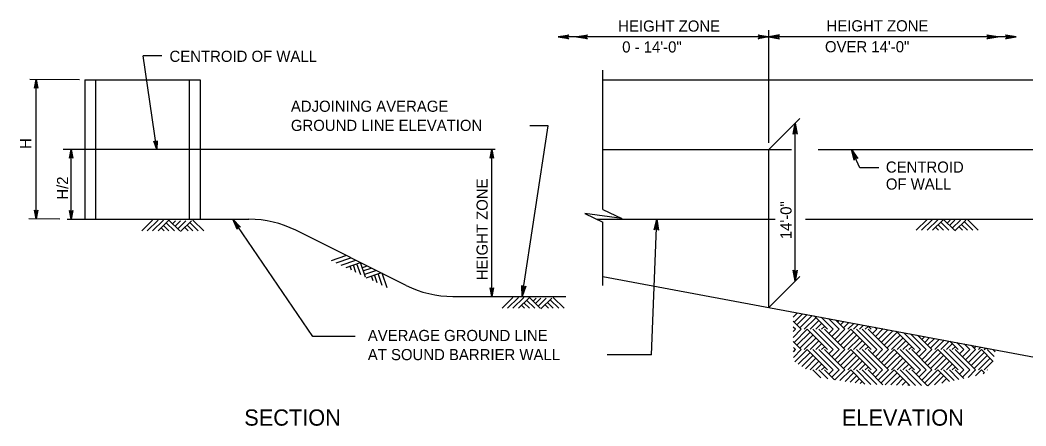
# Model space of a CAD drawing. Extents: x 3385 to 6532, y -616 to 1166.
# Drawn here: x 4114.7 to 4391.8, y 868.5 to 980.4 of the extents above; entities that cross this region are included whole.
import ezdxf

# ---------------------------------------------------------------- set-up
doc = ezdxf.new("R2010")
doc.units = 0
doc.layers.add('1', color=7, linetype='Continuous')

msp = doc.modelspace()

# ---------------------------------------------------------------- linework, layer by layer
at = {"layer": '1'}
for p, q in [((4389.13, 975.76), (4262.87, 975.76)), ((4320.95, 946.55), (4320.95, 977.59)), ((4153.71, 970.51), (4148.63, 970.51)), ((4152.34, 944.69), (4148.63, 970.51)), ((4275.26, 928.19), (4275.26, 966.59)), ((4131.05, 963.89), (4117.4, 964)), ((4119.09, 925.6), (4119.09, 964)), ((4132.47, 963.89), (4132.47, 925.49)), ((4132.47, 963.89), (4164.27, 963.89)), ((4135.47, 963.89), (4135.47, 925.49)), ((4161.27, 963.89), (4161.27, 925.49)), ((4164.27, 963.89), (4164.27, 925.49)), ((4275.26, 963.89), (4416.34, 963.89)), ((4320.95, 944.69), (4329.48, 953.22)), ((4253, 904.21), (4260.16, 951.24)), ((4260.16, 951.24), (4255.08, 951.24)), ((4328.22, 908.41), (4328.22, 951.96)), ((4245.56, 944.69), (4126.55, 944.69)), ((4128.74, 925.49), (4128.74, 944.69)), ((4244.62, 904.21), (4244.62, 944.69)), ((4275.26, 944.69), (4327.19, 944.69)), ((4320.95, 901.15), (4320.95, 944.69)), ((4334.55, 944.69), (4425.74, 944.69)), ((4346.02, 939.62), (4343.74, 944.69)), ((4351.29, 939.62), (4346.02, 939.62)), ((4125.61, 925.49), (4117.09, 925.56)), ((4127.65, 925.49), (4177.74, 925.49)), ((4195.37, 893.19), (4173.27, 925.49)), ((4273.54, 925.49), (4322.71, 925.49)), ((4288.66, 888.05), (4290.07, 925.49)), ((4331.03, 925.49), (4416.34, 925.49)), ((4361.55, 922.44), (4364.56, 925.45)), ((4363.05, 922.44), (4366.06, 925.45)), ((4364.55, 922.44), (4367.56, 925.45)), ((4366.05, 922.44), (4369.06, 925.45)), ((4372.06, 922.44), (4369.06, 925.45)), ((4378.65, 922.44), (4375.65, 925.45)), ((4148.18, 922.25), (4151.18, 925.26)), ((4149.68, 922.25), (4152.68, 925.26)), ((4151.18, 922.25), (4154.18, 925.26)), ((4152.68, 922.25), (4155.68, 925.26)), ((4154.36, 922.31), (4153.53, 923.14)), ((4155.68, 922.25), (4154.18, 923.76)), ((4157.18, 922.25), (4154.93, 924.51)), ((4158.68, 922.25), (4155.68, 925.26)), ((4157.53, 925.02), (4156.71, 924.2)), ((4158.86, 925.08), (4157.36, 923.58)), ((4160.36, 925.08), (4158.11, 922.83)), ((4161.86, 925.08), (4158.86, 922.08)), ((4160.95, 922.31), (4160.12, 923.14)), ((4162.27, 922.25), (4160.77, 923.76)), ((4163.77, 922.25), (4161.52, 924.51)), ((4165.27, 922.25), (4162.27, 925.26)), ((4275.26, 907.17), (4275.26, 924.69)), ((4367.73, 922.5), (4366.91, 923.33)), ((4369.06, 922.44), (4367.56, 923.95)), ((4370.56, 922.44), (4368.31, 924.7)), ((4370.91, 925.21), (4370.08, 924.39)), ((4372.23, 925.27), (4370.73, 923.77)), ((4373.73, 925.27), (4371.48, 923.02)), ((4375.23, 925.27), (4372.23, 922.27)), ((4374.32, 922.5), (4373.5, 923.33)), ((4375.65, 922.44), (4374.15, 923.95)), ((4377.15, 922.44), (4374.9, 924.7)), ((4221.02, 907.25), (4190.62, 922.45)), ((4200.44, 914.14), (4204.46, 915.5)), ((4201.78, 913.48), (4205.81, 914.84)), ((4203.13, 912.81), (4207.15, 914.17)), ((4204.47, 912.15), (4208.5, 913.51)), ((4206, 911.46), (4205.63, 912.56)), ((4207.17, 910.82), (4206.49, 912.83)), ((4208.51, 910.15), (4207.49, 913.17)), ((4209.86, 909.49), (4208.5, 913.51)), ((4210.05, 912.48), (4208.95, 912.1)), ((4211.27, 911.94), (4209.26, 911.26)), ((4212.61, 911.28), (4209.6, 910.26)), ((4213.96, 910.61), (4209.94, 909.25)), ((4211.91, 908.54), (4211.54, 909.64)), ((4213.08, 907.9), (4212.39, 909.91)), ((4214.42, 907.24), (4213.4, 910.25)), ((4215.77, 906.57), (4214.4, 910.59)), ((4275.26, 909.69), (4416.34, 883.3)), ((4320.95, 901.15), (4329.48, 909.68)), ((4233.9, 904.21), (4265, 904.21)), ((4247.46, 900.92), (4250.47, 903.92)), ((4248.96, 900.92), (4251.97, 903.92)), ((4250.46, 900.92), (4253.47, 903.92)), ((4251.96, 900.92), (4254.97, 903.92)), ((4257.97, 900.92), (4254.97, 903.92)), ((4256.82, 903.69), (4255.99, 902.86)), ((4258.14, 903.75), (4256.64, 902.24)), ((4259.64, 903.75), (4257.39, 901.49)), ((4261.14, 903.75), (4258.14, 900.74)), ((4264.56, 900.92), (4261.56, 903.92)), ((4253.64, 900.98), (4252.82, 901.8)), ((4254.97, 900.92), (4253.47, 902.42)), ((4256.47, 900.92), (4254.22, 903.17)), ((4260.23, 900.98), (4259.41, 901.8)), ((4261.56, 900.92), (4260.06, 902.42)), ((4263.06, 900.92), (4260.81, 903.17)), ((4327.65, 898.48), (4328.84, 899.67)), ((4327.9, 897.13), (4330.19, 899.42)), ((4328.7, 896.33), (4331.53, 899.17)), ((4329.5, 895.53), (4332.88, 898.91)), ((4330.7, 895.13), (4333.9, 898.33)), ((4337.1, 895.13), (4333.41, 898.81)), ((4338.7, 895.13), (4335.38, 898.45)), ((4340.3, 895.13), (4337.35, 898.08)), ((4329.9, 895.13), (4327.65, 897.37)), ((4328.3, 895.13), (4327.66, 895.76)), ((4327.67, 894.5), (4328.3, 895.13)), ((4327.68, 892.91), (4329.9, 895.13)), ((4327.9, 891.53), (4331.5, 895.13)), ((4337.1, 889.53), (4331.5, 895.13)), ((4332.3, 895.13), (4334.7, 897.53)), ((4338.7, 889.53), (4333.1, 895.13)), ((4333.9, 895.13), (4335.5, 896.73)), ((4340.3, 889.53), (4334.7, 895.13)), ((4335.5, 895.13), (4336.3, 895.93)), ((4341.9, 889.53), (4336.3, 895.13)), ((4337.5, 893.93), (4338.7, 895.13)), ((4338.3, 893.13), (4340.3, 895.13)), ((4339.1, 892.33), (4341.9, 895.13)), ((4341.9, 895.13), (4339.32, 897.71)), ((4339.9, 897.13), (4340.29, 897.53)), ((4339.9, 891.53), (4343.5, 895.13)), ((4340.7, 896.33), (4341.64, 897.27)), ((4341.5, 895.53), (4342.99, 897.02)), ((4342.7, 895.13), (4344.34, 896.77)), ((4349.1, 889.53), (4343.5, 895.13)), ((4344.3, 895.13), (4345.69, 896.52)), ((4350.7, 889.53), (4345.1, 895.13)), ((4345.9, 895.13), (4347.03, 896.27)), ((4352.3, 889.53), (4346.7, 895.13)), ((4347.5, 895.13), (4348.3, 895.93)), ((4349.1, 895.13), (4348.18, 896.05)), ((4353.9, 889.53), (4348.3, 895.13)), ((4349.5, 893.93), (4350.7, 895.13)), ((4350.7, 895.13), (4350.14, 895.68)), ((4350.3, 893.13), (4352.3, 895.13)), ((4351.1, 892.33), (4353.77, 895)), ((4352.3, 895.13), (4352.11, 895.31)), ((4206.95, 893.19), (4195.37, 893.19)), ((4328.7, 890.73), (4332.3, 894.33)), ((4329.5, 889.93), (4333.1, 893.53)), ((4330.7, 889.53), (4333.9, 892.73)), ((4340.7, 890.73), (4344.3, 894.33)), ((4341.5, 889.93), (4345.1, 893.53)), ((4342.7, 889.53), (4345.9, 892.73)), ((4351.9, 891.53), (4355.12, 894.75)), ((4352.7, 890.73), (4355.5, 893.53)), ((4355.5, 893.53), (4356.3, 894.33)), ((4355.5, 891.93), (4357.1, 893.53)), ((4355.5, 890.33), (4357.9, 892.73)), ((4361.1, 889.53), (4356.05, 894.58)), ((4362.7, 889.53), (4358.02, 894.21)), ((4364.3, 889.53), (4359.99, 893.84)), ((4365.9, 889.53), (4361.95, 893.47)), ((4362.3, 893.13), (4362.53, 893.36)), ((4363.1, 892.33), (4363.88, 893.11)), ((4363.9, 891.53), (4365.23, 892.86)), ((4364.7, 890.73), (4366.58, 892.61)), ((4365.5, 889.93), (4367.92, 892.36)), ((4329.9, 889.53), (4327.69, 891.74)), ((4328.3, 889.53), (4327.7, 890.13)), ((4327.71, 887.35), (4329.9, 889.53)), ((4327.71, 888.94), (4328.3, 889.53)), ((4328.08, 886.12), (4331.5, 889.53)), ((4337.1, 883.93), (4331.5, 889.53)), ((4332.3, 889.53), (4334.7, 891.93)), ((4338.7, 883.93), (4333.1, 889.53)), ((4333.9, 889.53), (4335.5, 891.13)), ((4340.3, 883.93), (4334.7, 889.53)), ((4335.5, 889.53), (4336.3, 890.33)), ((4341.9, 883.93), (4336.3, 889.53)), ((4337.5, 888.33), (4338.7, 889.53)), ((4338.3, 887.53), (4340.3, 889.53)), ((4339.1, 886.73), (4341.9, 889.53)), ((4339.9, 885.93), (4343.5, 889.53)), ((4349.1, 883.93), (4343.5, 889.53)), ((4344.3, 889.53), (4346.7, 891.93)), ((4350.7, 883.93), (4345.1, 889.53)), ((4345.9, 889.53), (4347.5, 891.13)), ((4352.3, 883.93), (4346.7, 889.53)), ((4347.5, 889.53), (4348.3, 890.33)), ((4353.9, 883.93), (4348.3, 889.53)), ((4349.5, 888.33), (4350.7, 889.53)), ((4350.3, 887.53), (4352.3, 889.53)), ((4351.1, 886.73), (4353.9, 889.53)), ((4351.9, 885.93), (4355.5, 889.53)), ((4353.5, 889.93), (4355.5, 891.93)), ((4354.7, 889.53), (4355.5, 890.33)), ((4361.1, 883.93), (4355.5, 889.53)), ((4356.3, 889.53), (4358.7, 891.93)), ((4362.7, 883.93), (4357.1, 889.53)), ((4357.9, 889.53), (4359.5, 891.13)), ((4364.3, 883.93), (4358.7, 889.53)), ((4359.5, 889.53), (4360.3, 890.33)), ((4365.9, 883.93), (4360.3, 889.53)), ((4361.5, 888.33), (4362.7, 889.53)), ((4362.3, 887.53), (4364.3, 889.53)), ((4363.1, 886.73), (4365.9, 889.53)), ((4363.9, 885.93), (4367.5, 889.53)), ((4366.7, 889.53), (4369.27, 892.1)), ((4373.1, 883.93), (4367.5, 889.53)), ((4368.3, 889.53), (4370.62, 891.85)), ((4374.7, 883.93), (4369.1, 889.53)), ((4369.9, 889.53), (4371.5, 891.13)), ((4376.3, 883.93), (4370.7, 889.53)), ((4373.1, 889.53), (4370.81, 891.82)), ((4371.5, 889.53), (4372.3, 890.33)), ((4377.9, 883.93), (4372.3, 889.53)), ((4374.7, 889.53), (4372.78, 891.45)), ((4373.5, 888.33), (4374.7, 889.53)), ((4374.3, 887.53), (4376.3, 889.53)), ((4376.3, 889.53), (4374.75, 891.08)), ((4375.1, 886.73), (4377.9, 889.53)), ((4375.9, 885.93), (4379.5, 889.53)), ((4377.9, 889.53), (4376.72, 890.71)), ((4377.5, 889.93), (4378.03, 890.46)), ((4378.7, 889.53), (4379.38, 890.21)), ((4382.74, 886.28), (4379.5, 889.53)), ((4380.3, 889.53), (4380.73, 889.96)), ((4383, 887.62), (4381.1, 889.53)), ((4381.9, 889.53), (4382.08, 889.71)), ((4383.27, 888.96), (4382.7, 889.53)), ((4288.66, 888.05), (4276.44, 888.05)), ((4329.07, 885.5), (4332.3, 888.73)), ((4330.05, 884.88), (4333.1, 887.93)), ((4331.03, 884.26), (4333.9, 887.13)), ((4340.7, 885.13), (4344.3, 888.73)), ((4341.5, 884.33), (4345.1, 887.93)), ((4342.7, 883.93), (4345.9, 887.13)), ((4352.7, 885.13), (4355.5, 887.93)), ((4355.5, 887.93), (4356.3, 888.73)), ((4355.5, 886.33), (4357.1, 887.93)), ((4355.5, 884.73), (4357.9, 887.13)), ((4364.7, 885.13), (4368.3, 888.73)), ((4365.5, 884.33), (4369.1, 887.93)), ((4366.7, 883.93), (4369.9, 887.13)), ((4376.7, 885.13), (4380.3, 888.73)), ((4377.5, 884.33), (4381.1, 887.93)), ((4378.7, 883.93), (4381.9, 887.13)), ((4332.3, 883.93), (4334.7, 886.33)), ((4335.31, 881.72), (4333.1, 883.93)), ((4333.9, 883.93), (4335.5, 885.53)), ((4337.17, 881.45), (4334.7, 883.93)), ((4335.5, 883.93), (4336.3, 884.73)), ((4339.04, 881.19), (4336.3, 883.93)), ((4337.5, 882.73), (4338.7, 883.93)), ((4338.3, 881.93), (4340.3, 883.93)), ((4339.14, 881.17), (4341.9, 883.93)), ((4340.54, 880.97), (4343.5, 883.93)), ((4347.44, 879.99), (4343.5, 883.93)), ((4344.3, 883.93), (4346.7, 886.33)), ((4349.09, 879.94), (4345.1, 883.93)), ((4345.9, 883.93), (4347.5, 885.53)), ((4350.73, 879.9), (4346.7, 883.93)), ((4347.5, 883.93), (4348.3, 884.73)), ((4352.37, 879.86), (4348.3, 883.93)), ((4349.5, 882.73), (4350.7, 883.93)), ((4350.3, 881.93), (4352.3, 883.93)), ((4351.1, 881.13), (4353.9, 883.93)), ((4351.9, 880.33), (4355.5, 883.93)), ((4353.5, 884.33), (4355.5, 886.33)), ((4354.7, 883.93), (4355.5, 884.73)), ((4359.75, 879.67), (4355.5, 883.93)), ((4356.3, 883.93), (4358.7, 886.33)), ((4361.39, 879.63), (4357.1, 883.93)), ((4357.9, 883.93), (4359.5, 885.53)), ((4363.04, 879.59), (4358.7, 883.93)), ((4359.5, 883.93), (4360.3, 884.73)), ((4364.68, 879.55), (4360.3, 883.93)), ((4361.5, 882.73), (4362.7, 883.93)), ((4362.3, 881.93), (4364.3, 883.93)), ((4363.1, 881.13), (4365.9, 883.93)), ((4363.9, 880.33), (4367.5, 883.93)), ((4370.7, 880.73), (4367.5, 883.93)), ((4368.3, 883.93), (4370.7, 886.33)), ((4372.01, 881.02), (4369.1, 883.93)), ((4369.9, 883.93), (4371.5, 885.53)), ((4373.32, 881.31), (4370.7, 883.93)), ((4371.5, 883.93), (4372.3, 884.73)), ((4374.63, 881.6), (4372.3, 883.93)), ((4373.5, 882.73), (4374.7, 883.93)), ((4374.3, 881.93), (4376.3, 883.93)), ((4375.83, 881.87), (4377.9, 883.93)), ((4377.89, 882.32), (4379.5, 883.93)), ((4380.32, 883.11), (4379.5, 883.93)), ((4380.3, 883.93), (4382.7, 886.33)), ((4381.17, 883.86), (4381.1, 883.93)), ((4341.94, 880.77), (4344.3, 883.13)), ((4343.34, 880.57), (4345.1, 882.33)), ((4344.74, 880.37), (4345.9, 881.53)), ((4353.01, 879.84), (4355.5, 882.33)), ((4355.5, 882.33), (4356.3, 883.13)), ((4355.5, 880.73), (4357.1, 882.33)), ((4356.13, 879.76), (4357.9, 881.53)), ((4364.72, 879.55), (4368.3, 883.13)), ((4366.59, 879.82), (4369.1, 882.33)), ((4368.64, 880.27), (4369.9, 881.53)), ((4380.03, 882.86), (4380.3, 883.13)), ((4346.14, 880.17), (4346.7, 880.73)), ((4354.57, 879.8), (4355.5, 880.73)), ((4357.69, 879.73), (4358.7, 880.73)), ((4359.26, 879.69), (4359.5, 879.93)), ((4370.7, 880.73), (4370.7, 880.73))]:
    msp.add_line(p, q, dxfattribs=at)
for points in [[(4262.87, 975.76), (4265.85, 976.32), (4265.74, 976.24), (4265.62, 976.16), (4265.56, 976.06), (4265.5, 975.96), (4265.48, 975.86), (4265.47, 975.76), (4265.48, 975.66), (4265.5, 975.56), (4265.56, 975.46), (4265.62, 975.36), (4265.74, 975.28), (4265.85, 975.2), (4262.87, 975.76), (4265.74, 975.28), (4265.62, 975.36), (4262.87, 975.76), (4265.56, 975.46), (4265.5, 975.56), (4262.87, 975.76), (4265.48, 975.66), (4265.47, 975.76), (4262.87, 975.76), (4265.48, 975.86), (4265.5, 975.96), (4262.87, 975.76), (4265.56, 976.06), (4265.62, 976.16), (4262.87, 975.76), (4265.74, 976.24)], [(4267.99, 975.76), (4270.97, 976.32), (4270.86, 976.24), (4270.74, 976.16), (4270.68, 976.06), (4270.62, 975.96), (4270.6, 975.86), (4270.59, 975.76), (4270.6, 975.66), (4270.62, 975.56), (4270.68, 975.46), (4270.74, 975.36), (4270.86, 975.28), (4270.97, 975.2), (4267.99, 975.76), (4270.86, 975.28), (4270.74, 975.36), (4267.99, 975.76), (4270.68, 975.46), (4270.62, 975.56), (4267.99, 975.76), (4270.6, 975.66), (4270.59, 975.76), (4267.99, 975.76), (4270.6, 975.86), (4270.62, 975.96), (4267.99, 975.76), (4270.68, 976.06), (4270.74, 976.16), (4267.99, 975.76), (4270.86, 976.24)], [(4320.95, 975.76), (4317.97, 975.2), (4318.2, 975.36), (4318.32, 975.56), (4318.35, 975.76), (4318.32, 975.96), (4318.2, 976.16), (4317.97, 976.32), (4320.95, 975.76), (4318.2, 976.16), (4318.32, 975.96), (4320.95, 975.76), (4318.35, 975.76), (4318.32, 975.56), (4320.95, 975.76), (4318.2, 975.36)], [(4320.95, 975.76), (4323.93, 975.2), (4323.7, 975.36), (4323.58, 975.56), (4323.55, 975.76), (4323.58, 975.96), (4323.7, 976.16), (4323.93, 976.32), (4320.95, 975.76), (4323.7, 976.16), (4323.58, 975.96), (4320.95, 975.76), (4323.55, 975.76), (4323.58, 975.56), (4320.95, 975.76), (4323.7, 975.36)], [(4384.01, 975.76), (4381.03, 975.2), (4381.14, 975.28), (4381.26, 975.36), (4381.31, 975.46), (4381.37, 975.56), (4381.39, 975.66), (4381.41, 975.76), (4381.39, 975.86), (4381.37, 975.96), (4381.31, 976.06), (4381.26, 976.16), (4381.14, 976.24), (4381.03, 976.32), (4384.01, 975.76), (4381.14, 976.24), (4381.26, 976.16), (4384.01, 975.76), (4381.31, 976.06), (4381.37, 975.96), (4384.01, 975.76), (4381.39, 975.86), (4381.41, 975.76), (4384.01, 975.76), (4381.39, 975.66), (4381.37, 975.56), (4384.01, 975.76), (4381.31, 975.46), (4381.26, 975.36), (4384.01, 975.76), (4381.14, 975.28)], [(4389.13, 975.76), (4386.15, 975.2), (4386.26, 975.28), (4386.38, 975.36), (4386.43, 975.46), (4386.49, 975.56), (4386.51, 975.66), (4386.53, 975.76), (4386.51, 975.86), (4386.49, 975.96), (4386.43, 976.06), (4386.38, 976.16), (4386.26, 976.24), (4386.15, 976.32), (4389.13, 975.76), (4386.26, 976.24), (4386.38, 976.16), (4389.13, 975.76), (4386.43, 976.06), (4386.49, 975.96), (4389.13, 975.76), (4386.51, 975.86), (4386.53, 975.76), (4389.13, 975.76), (4386.51, 975.66), (4386.49, 975.56), (4389.13, 975.76), (4386.43, 975.46), (4386.38, 975.36), (4389.13, 975.76), (4386.26, 975.28)], [(4119.09, 964), (4119.54, 961.61), (4119.48, 961.7), (4119.41, 961.8), (4119.33, 961.84), (4119.25, 961.89), (4119.17, 961.91), (4119.09, 961.92), (4119.01, 961.91), (4118.93, 961.89), (4118.85, 961.84), (4118.77, 961.8), (4118.71, 961.7), (4118.65, 961.61), (4119.09, 964), (4118.71, 961.7), (4118.77, 961.8), (4119.09, 964), (4118.85, 961.84), (4118.93, 961.89), (4119.09, 964), (4119.01, 961.91), (4119.09, 961.92), (4119.09, 964), (4119.17, 961.91), (4119.25, 961.89), (4119.09, 964), (4119.33, 961.84), (4119.41, 961.8), (4119.09, 964), (4119.48, 961.7)], [(4328.22, 951.96), (4328.78, 948.97), (4328.62, 949.2), (4328.42, 949.32), (4328.22, 949.36), (4328.02, 949.32), (4327.82, 949.2), (4327.66, 948.97), (4328.22, 951.96), (4327.82, 949.2), (4328.02, 949.32), (4328.22, 951.96), (4328.22, 949.36), (4328.42, 949.32), (4328.22, 951.96), (4328.62, 949.2)], [(4152.34, 944.69), (4151.55, 946.99), (4151.63, 946.9), (4151.71, 946.82), (4151.79, 946.79), (4151.88, 946.75), (4151.96, 946.75), (4152.04, 946.75), (4152.12, 946.77), (4152.2, 946.8), (4152.27, 946.85), (4152.34, 946.91), (4152.39, 947.01), (4152.44, 947.11), (4152.34, 944.69), (4152.39, 947.01), (4152.34, 946.91), (4152.34, 944.69), (4152.27, 946.85), (4152.2, 946.8), (4152.34, 944.69), (4152.12, 946.77), (4152.04, 946.75), (4152.34, 944.69), (4151.96, 946.75), (4151.88, 946.75), (4152.34, 944.69), (4151.79, 946.79), (4151.71, 946.82), (4152.34, 944.69), (4151.63, 946.9)], [(4128.74, 944.69), (4129.19, 942.3), (4129.13, 942.39), (4129.06, 942.49), (4128.98, 942.53), (4128.9, 942.58), (4128.82, 942.59), (4128.74, 942.61), (4128.66, 942.59), (4128.58, 942.58), (4128.5, 942.53), (4128.42, 942.49), (4128.36, 942.39), (4128.3, 942.3), (4128.74, 944.69), (4128.36, 942.39), (4128.42, 942.49), (4128.74, 944.69), (4128.5, 942.53), (4128.58, 942.58), (4128.74, 944.69), (4128.66, 942.59), (4128.74, 942.61), (4128.74, 944.69), (4128.82, 942.59), (4128.9, 942.58), (4128.74, 944.69), (4128.98, 942.53), (4129.06, 942.49), (4128.74, 944.69), (4129.13, 942.39)], [(4244.62, 944.69), (4245.07, 942.3), (4245.01, 942.39), (4244.94, 942.49), (4244.86, 942.53), (4244.78, 942.58), (4244.7, 942.59), (4244.62, 942.61), (4244.54, 942.59), (4244.46, 942.58), (4244.38, 942.53), (4244.3, 942.49), (4244.24, 942.39), (4244.17, 942.3), (4244.62, 944.69), (4244.24, 942.39), (4244.3, 942.49), (4244.62, 944.69), (4244.38, 942.53), (4244.46, 942.58), (4244.62, 944.69), (4244.54, 942.59), (4244.62, 942.61), (4244.62, 944.69), (4244.7, 942.59), (4244.78, 942.58), (4244.62, 944.69), (4244.86, 942.53), (4244.94, 942.49), (4244.62, 944.69), (4245.01, 942.39)], [(4343.74, 944.69), (4345.47, 942.2), (4345.23, 942.34), (4345, 942.37), (4344.81, 942.32), (4344.64, 942.2), (4344.5, 942.01), (4344.45, 941.74), (4343.74, 944.69), (4344.5, 942.01), (4344.64, 942.2), (4343.74, 944.69), (4344.81, 942.32), (4345, 942.37), (4343.74, 944.69), (4345.23, 942.34)], [(4119.09, 925.6), (4118.65, 927.98), (4118.71, 927.89), (4118.77, 927.8), (4118.85, 927.75), (4118.93, 927.71), (4119.01, 927.69), (4119.09, 927.68), (4119.17, 927.69), (4119.25, 927.71), (4119.33, 927.75), (4119.41, 927.8), (4119.48, 927.89), (4119.54, 927.98), (4119.09, 925.6), (4119.48, 927.89), (4119.41, 927.8), (4119.09, 925.6), (4119.33, 927.75), (4119.25, 927.71), (4119.09, 925.6), (4119.17, 927.69), (4119.09, 927.68), (4119.09, 925.6), (4119.01, 927.69), (4118.93, 927.71), (4119.09, 925.6), (4118.85, 927.75), (4118.77, 927.8), (4119.09, 925.6), (4118.71, 927.89)], [(4119.09, 925.6), (4118.65, 927.98), (4118.71, 927.89), (4118.77, 927.8), (4118.85, 927.75), (4118.93, 927.71), (4119.01, 927.69), (4119.09, 927.68), (4119.17, 927.69), (4119.25, 927.71), (4119.33, 927.75), (4119.41, 927.8), (4119.48, 927.89), (4119.54, 927.98), (4119.09, 925.6), (4119.48, 927.89), (4119.41, 927.8), (4119.09, 925.6), (4119.33, 927.75), (4119.25, 927.71), (4119.09, 925.6), (4119.17, 927.69), (4119.09, 927.68), (4119.09, 925.6), (4119.01, 927.69), (4118.93, 927.71), (4119.09, 925.6), (4118.85, 927.75), (4118.77, 927.8), (4119.09, 925.6), (4118.71, 927.89)], [(4128.74, 925.49), (4128.3, 927.87), (4128.36, 927.78), (4128.42, 927.69), (4128.5, 927.64), (4128.58, 927.59), (4128.66, 927.58), (4128.74, 927.57), (4128.82, 927.58), (4128.9, 927.59), (4128.98, 927.64), (4129.06, 927.69), (4129.13, 927.78), (4129.19, 927.87), (4128.74, 925.49), (4129.13, 927.78), (4129.06, 927.69), (4128.74, 925.49), (4128.98, 927.64), (4128.9, 927.59), (4128.74, 925.49), (4128.82, 927.58), (4128.74, 927.57), (4128.74, 925.49), (4128.66, 927.58), (4128.58, 927.59), (4128.74, 925.49), (4128.5, 927.64), (4128.42, 927.69), (4128.74, 925.49), (4128.36, 927.78)], [(4173.27, 925.49), (4175.41, 923.34), (4175.28, 923.39), (4175.15, 923.44), (4175.03, 923.43), (4174.92, 923.43), (4174.83, 923.38), (4174.73, 923.34), (4174.66, 923.27), (4174.59, 923.2), (4174.54, 923.09), (4174.49, 922.99), (4174.49, 922.85), (4174.49, 922.71), (4173.27, 925.49), (4174.49, 922.85), (4174.49, 922.99), (4173.27, 925.49), (4174.54, 923.09), (4174.59, 923.2), (4173.27, 925.49), (4174.66, 923.27), (4174.73, 923.34), (4173.27, 925.49), (4174.83, 923.38), (4174.92, 923.43), (4173.27, 925.49), (4175.03, 923.43), (4175.15, 923.44), (4173.27, 925.49), (4175.28, 923.39)], [(4275.26, 928.19), (4280.45, 925.65), (4270.3, 927.03), (4275.26, 924.67)], [(4290.07, 925.49), (4290.51, 922.49), (4290.44, 922.6), (4290.36, 922.72), (4290.27, 922.78), (4290.17, 922.85), (4290.07, 922.87), (4289.97, 922.89), (4289.87, 922.88), (4289.77, 922.86), (4289.67, 922.81), (4289.56, 922.75), (4289.48, 922.64), (4289.4, 922.53), (4290.07, 925.49), (4289.48, 922.64), (4289.56, 922.75), (4290.07, 925.49), (4289.67, 922.81), (4289.77, 922.86), (4290.07, 925.49), (4289.87, 922.88), (4289.97, 922.89), (4290.07, 925.49), (4290.07, 922.87), (4290.17, 922.85), (4290.07, 925.49), (4290.27, 922.78), (4290.36, 922.72), (4290.07, 925.49), (4290.44, 922.6)], [(4328.22, 908.41), (4327.66, 911.4), (4327.82, 911.17), (4328.02, 911.05), (4328.22, 911.01), (4328.42, 911.05), (4328.62, 911.17), (4328.78, 911.4), (4328.22, 908.41), (4328.62, 911.17), (4328.42, 911.05), (4328.22, 908.41), (4328.22, 911.01), (4328.02, 911.05), (4328.22, 908.41), (4327.82, 911.17)], [(4244.62, 904.21), (4244.17, 906.59), (4244.24, 906.5), (4244.3, 906.41), (4244.38, 906.36), (4244.46, 906.31), (4244.54, 906.3), (4244.62, 906.29), (4244.7, 906.3), (4244.78, 906.31), (4244.86, 906.36), (4244.94, 906.41), (4245.01, 906.5), (4245.07, 906.59), (4244.62, 904.21), (4245.01, 906.5), (4244.94, 906.41), (4244.62, 904.21), (4244.86, 906.36), (4244.78, 906.31), (4244.62, 904.21), (4244.7, 906.3), (4244.62, 906.29), (4244.62, 904.21), (4244.54, 906.3), (4244.46, 906.31), (4244.62, 904.21), (4244.38, 906.36), (4244.3, 906.41), (4244.62, 904.21), (4244.24, 906.5)], [(4253, 904.21), (4252.89, 907.24), (4252.95, 907.11), (4253.02, 906.99), (4253.11, 906.91), (4253.2, 906.84), (4253.29, 906.81), (4253.39, 906.78), (4253.49, 906.78), (4253.59, 906.78), (4253.7, 906.82), (4253.81, 906.87), (4253.9, 906.97), (4254, 907.07), (4253, 904.21), (4253.9, 906.97), (4253.81, 906.87), (4253, 904.21), (4253.7, 906.82), (4253.59, 906.78), (4253, 904.21), (4253.49, 906.78), (4253.39, 906.78), (4253, 904.21), (4253.29, 906.81), (4253.2, 906.84), (4253, 904.21), (4253.11, 906.91), (4253.02, 906.99), (4253, 904.21), (4252.95, 907.11)]]:
    msp.add_lwpolyline(points, dxfattribs=at)
for centre, start, end in [((4177.74, 896.69), 63.4349, 90), ((4233.9, 933.01), 243.4349, 270)]:
    msp.add_arc(centre, 28.8, start, end, dxfattribs=at)

# ---------------------------------------------------------------- texts
for s, height, p in [('HEIGHT ZONE', 3.072, (4279.45, 977.22)), ('HEIGHT ZONE', 3.072, (4336.84, 977.28)), ('0 - 14\'-0"', 3.072, (4280.55, 971.46)), ('OVER 14\'-0"', 3.072, (4336.41, 971.52)), ('CENTROID OF WALL', 3.072, (4155.84, 968.88)), ('ADJOINING AVERAGE', 3.072, (4189.28, 955.11)), ('GROUND LINE ELEVATION', 3.072, (4189.28, 949.83)), ('CENTROID', 3.072, (4353.19, 938.33)), ('OF WALL', 3.072, (4353.19, 933.65)), ('AVERAGE GROUND LINE', 3.072, (4210.47, 891.89)), ('AT SOUND BARRIER WALL', 3.072, (4210.47, 886.62)), ('SECTION', 4.477, (4176.44, 868.56)), ('ELEVATION', 4.477, (4341.06, 868.56))]:
    msp.add_text(s, height=height, dxfattribs=at).set_placement(p)
for s, height, p in [('H', 3.07, (4117.76, 944.85)), ('H/2', 3.072, (4127.92, 930.87)), ('HEIGHT ZONE', 3.072, (4243.5, 908.64)), ('14\'-0"', 3.072, (4327.21, 919.98))]:
    msp.add_text(s, height=height, rotation=90, dxfattribs=at).set_placement(p)

doc.saveas('drawing.dxf')
